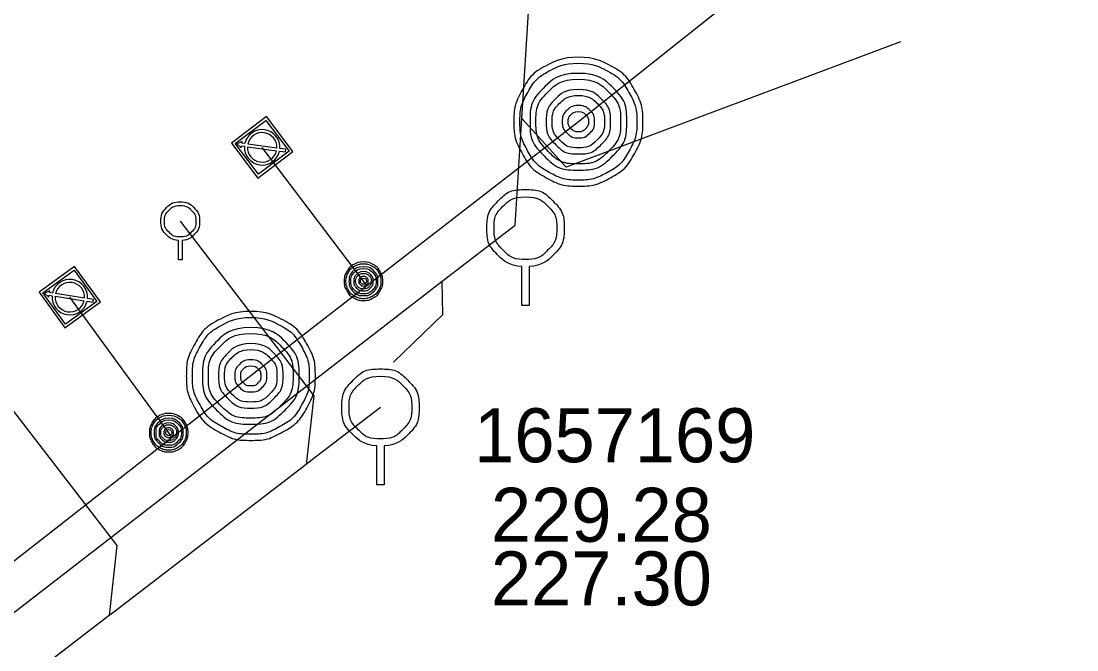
# Model space of a CAD drawing. Extents: x -595129 to -593591, y -1168385 to -1166898.
# Drawn here: x -594577.44 to -594550.08, y -1167330.38 to -1167314.08 of the extents above; entities that cross this region are included whole.
import ezdxf

# ---------------------------------------------------------------- set-up
doc = ezdxf.new("R2010")
doc.units = 0
for name, color, linetype in [('Default', 7, 'Continuous'), ('Identifikace', 7, 'Continuous'), ('Kanalizační přípojka', 7, 'Continuous'), ('Kanalizační stoka', 7, 'Continuous'), ('Kanalizační šachta', 7, 'Continuous'), ('Popis šachty', 7, 'Continuous'), ('V Odběrné místo', 7, 'Continuous'), ('V Přípojka', 7, 'Continuous'), ('V Řad', 7, 'Continuous')]:
    doc.layers.add(name, color=color, linetype=linetype)

msp = doc.modelspace()

# ---------------------------------------------------------------- linework, layer by layer
at = {"layer": 'Default'}
for points in [[(-594563.002, -1167315.017), (-594562.58, -1167315.017), (-594562.181, -1167315.232), (-594561.781, -1167315.448), (-594561.554, -1167315.85), (-594561.328, -1167316.253), (-594561.328, -1167316.69), (-594561.328, -1167317.124), (-594561.549, -1167317.522), (-594561.769, -1167317.919), (-594562.167, -1167318.14), (-594562.566, -1167318.36), (-594563.002, -1167318.36), (-594563.434, -1167318.36), (-594563.833, -1167318.14), (-594564.231, -1167317.919), (-594564.451, -1167317.522), (-594564.672, -1167317.124), (-594564.672, -1167316.69), (-594564.672, -1167316.253), (-594564.447, -1167315.85), (-594564.223, -1167315.448), (-594563.824, -1167315.232), (-594563.424, -1167315.017), (-594563.002, -1167315.017)], [(-594563.002, -1167315.173), (-594563.384, -1167315.173), (-594563.746, -1167315.369), (-594564.108, -1167315.564), (-594564.312, -1167315.928), (-594564.515, -1167316.293), (-594564.515, -1167316.69), (-594564.515, -1167317.083), (-594564.316, -1167317.443), (-594564.117, -1167317.803), (-594563.755, -1167318.003), (-594563.393, -1167318.203), (-594563.002, -1167318.203), (-594562.607, -1167318.203), (-594562.245, -1167318.003), (-594561.883, -1167317.803), (-594561.684, -1167317.443), (-594561.485, -1167317.083), (-594561.485, -1167316.69), (-594561.485, -1167316.293), (-594561.691, -1167315.928), (-594561.896, -1167315.564), (-594562.258, -1167315.369), (-594562.62, -1167315.173), (-594563.002, -1167315.173)], [(-594563.003, -1167315.435), (-594562.476, -1167315.435), (-594562.111, -1167315.802), (-594561.746, -1167316.169), (-594561.746, -1167316.69), (-594561.746, -1167317.209), (-594562.114, -1167317.576), (-594562.481, -1167317.942), (-594563.003, -1167317.942), (-594563.519, -1167317.942), (-594563.886, -1167317.576), (-594564.254, -1167317.209), (-594564.254, -1167316.69), (-594564.254, -1167316.169), (-594563.89, -1167315.802), (-594563.526, -1167315.435), (-594563.003, -1167315.435)], [(-594563.003, -1167315.588), (-594563.46, -1167315.588), (-594563.78, -1167315.909), (-594564.1, -1167316.23), (-594564.1, -1167316.685), (-594564.1, -1167317.141), (-594563.78, -1167317.461), (-594563.46, -1167317.782), (-594563.003, -1167317.782), (-594562.548, -1167317.782), (-594562.227, -1167317.461), (-594561.906, -1167317.141), (-594561.906, -1167316.685), (-594561.906, -1167316.23), (-594562.225, -1167315.909), (-594562.545, -1167315.588), (-594563.003, -1167315.588)], [(-594563.002, -1167315.853), (-594562.651, -1167315.853), (-594562.407, -1167316.097), (-594562.164, -1167316.342), (-594562.164, -1167316.69), (-594562.164, -1167317.036), (-594562.409, -1167317.28), (-594562.654, -1167317.524), (-594563.002, -1167317.524), (-594563.346, -1167317.524), (-594563.591, -1167317.28), (-594563.836, -1167317.036), (-594563.836, -1167316.69), (-594563.836, -1167316.342), (-594563.593, -1167316.097), (-594563.351, -1167315.853), (-594563.002, -1167315.853)], [(-594563.002, -1167316.008), (-594563.284, -1167316.008), (-594563.482, -1167316.206), (-594563.681, -1167316.404), (-594563.681, -1167316.687), (-594563.681, -1167316.969), (-594563.482, -1167317.167), (-594563.284, -1167317.366), (-594563.002, -1167317.366), (-594562.721, -1167317.366), (-594562.522, -1167317.167), (-594562.323, -1167316.969), (-594562.323, -1167316.687), (-594562.323, -1167316.404), (-594562.521, -1167316.206), (-594562.719, -1167316.008), (-594563.002, -1167316.008)], [(-594563.002, -1167316.27), (-594562.825, -1167316.27), (-594562.704, -1167316.393), (-594562.582, -1167316.515), (-594562.582, -1167316.688), (-594562.582, -1167316.861), (-594562.705, -1167316.984), (-594562.827, -1167317.106), (-594563.002, -1167317.106), (-594563.173, -1167317.106), (-594563.295, -1167316.984), (-594563.418, -1167316.861), (-594563.418, -1167316.688), (-594563.418, -1167316.515), (-594563.296, -1167316.393), (-594563.175, -1167316.27), (-594563.002, -1167316.27)], [(-594563.002, -1167316.427), (-594563.109, -1167316.427), (-594563.186, -1167316.502), (-594563.263, -1167316.577), (-594563.263, -1167316.688), (-594563.263, -1167316.796), (-594563.186, -1167316.873), (-594563.109, -1167316.95), (-594563.002, -1167316.95), (-594562.891, -1167316.95), (-594562.816, -1167316.873), (-594562.74, -1167316.796), (-594562.74, -1167316.688), (-594562.74, -1167316.577), (-594562.816, -1167316.502), (-594562.891, -1167316.427), (-594563.002, -1167316.427)], [(-594564.464, -1167320.446), (-594564.817, -1167320.417), (-594565.077, -1167320.157), (-594565.37, -1167319.866), (-594565.37, -1167319.452), (-594565.37, -1167319.036), (-594565.08, -1167318.743), (-594564.79, -1167318.45), (-594564.372, -1167318.45), (-594563.952, -1167318.45), (-594563.661, -1167318.743), (-594563.37, -1167319.036), (-594563.37, -1167319.452), (-594563.37, -1167319.866), (-594563.663, -1167320.157), (-594563.921, -1167320.417), (-594564.276, -1167320.446)], [(-594564.372, -1167318.636), (-594564.71, -1167318.636), (-594564.947, -1167318.873), (-594565.184, -1167319.11), (-594565.184, -1167319.448), (-594565.184, -1167319.786), (-594564.947, -1167320.023), (-594564.71, -1167320.261), (-594564.372, -1167320.261), (-594564.034, -1167320.261), (-594563.797, -1167320.023), (-594563.559, -1167319.786), (-594563.559, -1167319.448), (-594563.559, -1167319.11), (-594563.796, -1167318.873), (-594564.032, -1167318.636), (-594564.372, -1167318.636)], [(-594573.367, -1167319.768), (-594573.544, -1167319.753), (-594573.674, -1167319.624), (-594573.82, -1167319.478), (-594573.82, -1167319.271), (-594573.82, -1167319.063), (-594573.675, -1167318.916), (-594573.53, -1167318.77), (-594573.321, -1167318.77), (-594573.111, -1167318.77), (-594572.966, -1167318.916), (-594572.82, -1167319.063), (-594572.82, -1167319.271), (-594572.82, -1167319.478), (-594572.966, -1167319.624), (-594573.095, -1167319.753), (-594573.273, -1167319.768)], [(-594573.321, -1167318.863), (-594573.49, -1167318.863), (-594573.609, -1167318.981), (-594573.727, -1167319.1), (-594573.727, -1167319.269), (-594573.727, -1167319.438), (-594573.609, -1167319.557), (-594573.49, -1167319.675), (-594573.321, -1167319.675), (-594573.152, -1167319.675), (-594573.033, -1167319.557), (-594572.915, -1167319.438), (-594572.915, -1167319.269), (-594572.915, -1167319.1), (-594573.033, -1167318.981), (-594573.151, -1167318.863), (-594573.321, -1167318.863)], [(-594568.571, -1167320.323), (-594568.445, -1167320.323), (-594568.325, -1167320.388), (-594568.205, -1167320.452), (-594568.138, -1167320.573), (-594568.07, -1167320.693), (-594568.07, -1167320.824), (-594568.07, -1167320.954), (-594568.136, -1167321.073), (-594568.202, -1167321.192), (-594568.321, -1167321.258), (-594568.44, -1167321.324), (-594568.571, -1167321.324), (-594568.7, -1167321.324), (-594568.82, -1167321.258), (-594568.939, -1167321.192), (-594569.005, -1167321.073), (-594569.071, -1167320.954), (-594569.071, -1167320.824), (-594569.071, -1167320.693), (-594569.004, -1167320.573), (-594568.936, -1167320.452), (-594568.817, -1167320.388), (-594568.697, -1167320.323), (-594568.571, -1167320.323)], [(-594568.571, -1167320.37), (-594568.685, -1167320.37), (-594568.794, -1167320.429), (-594568.902, -1167320.487), (-594568.963, -1167320.596), (-594569.024, -1167320.705), (-594569.024, -1167320.824), (-594569.024, -1167320.942), (-594568.964, -1167321.05), (-594568.905, -1167321.158), (-594568.796, -1167321.217), (-594568.688, -1167321.277), (-594568.571, -1167321.277), (-594568.453, -1167321.277), (-594568.344, -1167321.217), (-594568.236, -1167321.158), (-594568.176, -1167321.05), (-594568.117, -1167320.942), (-594568.117, -1167320.824), (-594568.117, -1167320.705), (-594568.178, -1167320.596), (-594568.24, -1167320.487), (-594568.348, -1167320.429), (-594568.456, -1167320.37), (-594568.571, -1167320.37)], [(-594568.571, -1167320.448), (-594568.413, -1167320.448), (-594568.304, -1167320.558), (-594568.195, -1167320.668), (-594568.195, -1167320.824), (-594568.195, -1167320.98), (-594568.305, -1167321.089), (-594568.415, -1167321.199), (-594568.571, -1167321.199), (-594568.726, -1167321.199), (-594568.836, -1167321.089), (-594568.946, -1167320.98), (-594568.946, -1167320.824), (-594568.946, -1167320.668), (-594568.837, -1167320.558), (-594568.728, -1167320.448), (-594568.571, -1167320.448)], [(-594568.571, -1167320.494), (-594568.708, -1167320.494), (-594568.804, -1167320.59), (-594568.9, -1167320.686), (-594568.9, -1167320.823), (-594568.9, -1167320.959), (-594568.804, -1167321.055), (-594568.708, -1167321.151), (-594568.571, -1167321.151), (-594568.435, -1167321.151), (-594568.339, -1167321.055), (-594568.243, -1167320.959), (-594568.243, -1167320.823), (-594568.243, -1167320.686), (-594568.338, -1167320.59), (-594568.434, -1167320.494), (-594568.571, -1167320.494)], [(-594568.571, -1167320.574), (-594568.466, -1167320.574), (-594568.393, -1167320.647), (-594568.32, -1167320.72), (-594568.32, -1167320.824), (-594568.32, -1167320.928), (-594568.393, -1167321.001), (-594568.467, -1167321.074), (-594568.571, -1167321.074), (-594568.674, -1167321.074), (-594568.747, -1167321.001), (-594568.821, -1167320.928), (-594568.821, -1167320.824), (-594568.821, -1167320.72), (-594568.748, -1167320.647), (-594568.675, -1167320.574), (-594568.571, -1167320.574)], [(-594568.571, -1167320.62), (-594568.655, -1167320.62), (-594568.715, -1167320.679), (-594568.774, -1167320.739), (-594568.774, -1167320.823), (-594568.774, -1167320.908), (-594568.715, -1167320.967), (-594568.655, -1167321.027), (-594568.571, -1167321.027), (-594568.487, -1167321.027), (-594568.427, -1167320.967), (-594568.367, -1167320.908), (-594568.367, -1167320.823), (-594568.367, -1167320.739), (-594568.427, -1167320.679), (-594568.486, -1167320.62), (-594568.571, -1167320.62)], [(-594568.571, -1167320.699), (-594568.518, -1167320.699), (-594568.482, -1167320.735), (-594568.445, -1167320.772), (-594568.445, -1167320.824), (-594568.445, -1167320.876), (-594568.482, -1167320.912), (-594568.519, -1167320.949), (-594568.571, -1167320.949), (-594568.622, -1167320.949), (-594568.659, -1167320.912), (-594568.695, -1167320.876), (-594568.695, -1167320.824), (-594568.695, -1167320.772), (-594568.659, -1167320.735), (-594568.623, -1167320.699), (-594568.571, -1167320.699)], [(-594568.571, -1167320.746), (-594568.603, -1167320.746), (-594568.626, -1167320.768), (-594568.649, -1167320.791), (-594568.649, -1167320.824), (-594568.649, -1167320.856), (-594568.626, -1167320.879), (-594568.603, -1167320.902), (-594568.571, -1167320.902), (-594568.538, -1167320.902), (-594568.515, -1167320.879), (-594568.493, -1167320.856), (-594568.493, -1167320.824), (-594568.493, -1167320.791), (-594568.515, -1167320.768), (-594568.538, -1167320.746), (-594568.571, -1167320.746)], [(-594571.492, -1167321.607), (-594571.07, -1167321.607), (-594570.671, -1167321.822), (-594570.271, -1167322.038), (-594570.044, -1167322.44), (-594569.818, -1167322.843), (-594569.818, -1167323.28), (-594569.818, -1167323.714), (-594570.039, -1167324.112), (-594570.259, -1167324.509), (-594570.657, -1167324.73), (-594571.056, -1167324.95), (-594571.492, -1167324.95), (-594571.924, -1167324.95), (-594572.323, -1167324.73), (-594572.721, -1167324.509), (-594572.941, -1167324.112), (-594573.162, -1167323.714), (-594573.162, -1167323.28), (-594573.162, -1167322.843), (-594572.937, -1167322.44), (-594572.713, -1167322.038), (-594572.314, -1167321.822), (-594571.914, -1167321.607), (-594571.492, -1167321.607)], [(-594571.492, -1167321.763), (-594571.874, -1167321.763), (-594572.236, -1167321.959), (-594572.598, -1167322.154), (-594572.802, -1167322.518), (-594573.005, -1167322.883), (-594573.005, -1167323.28), (-594573.005, -1167323.673), (-594572.806, -1167324.033), (-594572.607, -1167324.393), (-594572.245, -1167324.593), (-594571.883, -1167324.793), (-594571.492, -1167324.793), (-594571.097, -1167324.793), (-594570.735, -1167324.593), (-594570.373, -1167324.393), (-594570.174, -1167324.033), (-594569.975, -1167323.673), (-594569.975, -1167323.28), (-594569.975, -1167322.883), (-594570.181, -1167322.518), (-594570.386, -1167322.154), (-594570.748, -1167321.959), (-594571.11, -1167321.763), (-594571.492, -1167321.763)], [(-594571.493, -1167322.025), (-594570.966, -1167322.025), (-594570.601, -1167322.392), (-594570.236, -1167322.759), (-594570.236, -1167323.28), (-594570.236, -1167323.799), (-594570.604, -1167324.166), (-594570.971, -1167324.532), (-594571.493, -1167324.532), (-594572.009, -1167324.532), (-594572.376, -1167324.166), (-594572.744, -1167323.799), (-594572.744, -1167323.28), (-594572.744, -1167322.759), (-594572.38, -1167322.392), (-594572.016, -1167322.025), (-594571.493, -1167322.025)], [(-594571.493, -1167322.178), (-594571.95, -1167322.178), (-594572.27, -1167322.499), (-594572.59, -1167322.82), (-594572.59, -1167323.275), (-594572.59, -1167323.731), (-594572.27, -1167324.051), (-594571.95, -1167324.372), (-594571.493, -1167324.372), (-594571.038, -1167324.372), (-594570.717, -1167324.051), (-594570.396, -1167323.731), (-594570.396, -1167323.275), (-594570.396, -1167322.82), (-594570.715, -1167322.499), (-594571.035, -1167322.178), (-594571.493, -1167322.178)], [(-594571.492, -1167322.443), (-594571.141, -1167322.443), (-594570.897, -1167322.687), (-594570.654, -1167322.932), (-594570.654, -1167323.28), (-594570.654, -1167323.626), (-594570.899, -1167323.87), (-594571.144, -1167324.114), (-594571.492, -1167324.114), (-594571.836, -1167324.114), (-594572.081, -1167323.87), (-594572.326, -1167323.626), (-594572.326, -1167323.28), (-594572.326, -1167322.932), (-594572.083, -1167322.687), (-594571.841, -1167322.443), (-594571.492, -1167322.443)], [(-594571.492, -1167322.598), (-594571.774, -1167322.598), (-594571.972, -1167322.796), (-594572.171, -1167322.994), (-594572.171, -1167323.277), (-594572.171, -1167323.559), (-594571.972, -1167323.757), (-594571.774, -1167323.956), (-594571.492, -1167323.956), (-594571.211, -1167323.956), (-594571.012, -1167323.757), (-594570.813, -1167323.559), (-594570.813, -1167323.277), (-594570.813, -1167322.994), (-594571.011, -1167322.796), (-594571.209, -1167322.598), (-594571.492, -1167322.598)], [(-594571.492, -1167322.86), (-594571.315, -1167322.86), (-594571.194, -1167322.983), (-594571.072, -1167323.105), (-594571.072, -1167323.278), (-594571.072, -1167323.451), (-594571.195, -1167323.574), (-594571.317, -1167323.696), (-594571.492, -1167323.696), (-594571.663, -1167323.696), (-594571.785, -1167323.574), (-594571.908, -1167323.451), (-594571.908, -1167323.278), (-594571.908, -1167323.105), (-594571.786, -1167322.983), (-594571.665, -1167322.86), (-594571.492, -1167322.86)], [(-594571.492, -1167323.017), (-594571.599, -1167323.017), (-594571.676, -1167323.092), (-594571.753, -1167323.167), (-594571.753, -1167323.278), (-594571.753, -1167323.386), (-594571.676, -1167323.463), (-594571.599, -1167323.54), (-594571.492, -1167323.54), (-594571.381, -1167323.54), (-594571.306, -1167323.463), (-594571.23, -1167323.386), (-594571.23, -1167323.278), (-594571.23, -1167323.167), (-594571.306, -1167323.092), (-594571.381, -1167323.017), (-594571.492, -1167323.017)], [(-594568.224, -1167325.096), (-594568.577, -1167325.067), (-594568.837, -1167324.807), (-594569.13, -1167324.516), (-594569.13, -1167324.102), (-594569.13, -1167323.686), (-594568.84, -1167323.393), (-594568.55, -1167323.1), (-594568.132, -1167323.1), (-594567.712, -1167323.1), (-594567.421, -1167323.393), (-594567.13, -1167323.686), (-594567.13, -1167324.102), (-594567.13, -1167324.516), (-594567.423, -1167324.807), (-594567.681, -1167325.067), (-594568.036, -1167325.096)], [(-594568.132, -1167323.286), (-594568.47, -1167323.286), (-594568.707, -1167323.523), (-594568.944, -1167323.76), (-594568.944, -1167324.098), (-594568.944, -1167324.436), (-594568.707, -1167324.673), (-594568.47, -1167324.911), (-594568.132, -1167324.911), (-594567.794, -1167324.911), (-594567.557, -1167324.673), (-594567.319, -1167324.436), (-594567.319, -1167324.098), (-594567.319, -1167323.76), (-594567.556, -1167323.523), (-594567.792, -1167323.286), (-594568.132, -1167323.286)], [(-594573.619, -1167324.25), (-594573.493, -1167324.25), (-594573.373, -1167324.315), (-594573.253, -1167324.379), (-594573.186, -1167324.5), (-594573.118, -1167324.62), (-594573.118, -1167324.751), (-594573.118, -1167324.881), (-594573.184, -1167325), (-594573.25, -1167325.119), (-594573.369, -1167325.185), (-594573.488, -1167325.251), (-594573.619, -1167325.251), (-594573.749, -1167325.251), (-594573.868, -1167325.185), (-594573.987, -1167325.119), (-594574.053, -1167325), (-594574.119, -1167324.881), (-594574.119, -1167324.751), (-594574.119, -1167324.62), (-594574.052, -1167324.5), (-594573.985, -1167324.379), (-594573.865, -1167324.315), (-594573.746, -1167324.25), (-594573.619, -1167324.25)], [(-594573.619, -1167324.297), (-594573.733, -1167324.297), (-594573.842, -1167324.355), (-594573.95, -1167324.414), (-594574.011, -1167324.523), (-594574.072, -1167324.632), (-594574.072, -1167324.751), (-594574.072, -1167324.869), (-594574.012, -1167324.977), (-594573.953, -1167325.084), (-594573.845, -1167325.144), (-594573.736, -1167325.204), (-594573.619, -1167325.204), (-594573.501, -1167325.204), (-594573.392, -1167325.144), (-594573.284, -1167325.084), (-594573.225, -1167324.977), (-594573.165, -1167324.869), (-594573.165, -1167324.751), (-594573.165, -1167324.632), (-594573.227, -1167324.523), (-594573.288, -1167324.414), (-594573.396, -1167324.355), (-594573.505, -1167324.297), (-594573.619, -1167324.297)], [(-594573.619, -1167324.375), (-594573.462, -1167324.375), (-594573.352, -1167324.485), (-594573.243, -1167324.595), (-594573.243, -1167324.751), (-594573.243, -1167324.907), (-594573.353, -1167325.016), (-594573.463, -1167325.126), (-594573.619, -1167325.126), (-594573.774, -1167325.126), (-594573.884, -1167325.016), (-594573.994, -1167324.907), (-594573.994, -1167324.751), (-594573.994, -1167324.595), (-594573.885, -1167324.485), (-594573.776, -1167324.375), (-594573.619, -1167324.375)], [(-594573.619, -1167324.421), (-594573.756, -1167324.421), (-594573.852, -1167324.517), (-594573.948, -1167324.613), (-594573.948, -1167324.75), (-594573.948, -1167324.886), (-594573.852, -1167324.982), (-594573.756, -1167325.078), (-594573.619, -1167325.078), (-594573.483, -1167325.078), (-594573.387, -1167324.982), (-594573.291, -1167324.886), (-594573.291, -1167324.75), (-594573.291, -1167324.613), (-594573.387, -1167324.517), (-594573.482, -1167324.421), (-594573.619, -1167324.421)], [(-594573.619, -1167324.5), (-594573.514, -1167324.5), (-594573.441, -1167324.574), (-594573.368, -1167324.647), (-594573.368, -1167324.751), (-594573.368, -1167324.855), (-594573.442, -1167324.928), (-594573.515, -1167325.001), (-594573.619, -1167325.001), (-594573.722, -1167325.001), (-594573.795, -1167324.928), (-594573.869, -1167324.855), (-594573.869, -1167324.751), (-594573.869, -1167324.647), (-594573.796, -1167324.574), (-594573.724, -1167324.5), (-594573.619, -1167324.5)], [(-594573.619, -1167324.547), (-594573.704, -1167324.547), (-594573.763, -1167324.606), (-594573.822, -1167324.666), (-594573.822, -1167324.75), (-594573.822, -1167324.835), (-594573.763, -1167324.894), (-594573.704, -1167324.953), (-594573.619, -1167324.953), (-594573.535, -1167324.953), (-594573.475, -1167324.894), (-594573.416, -1167324.835), (-594573.416, -1167324.75), (-594573.416, -1167324.666), (-594573.475, -1167324.606), (-594573.534, -1167324.547), (-594573.619, -1167324.547)], [(-594573.619, -1167324.626), (-594573.566, -1167324.626), (-594573.53, -1167324.662), (-594573.493, -1167324.699), (-594573.493, -1167324.751), (-594573.493, -1167324.802), (-594573.53, -1167324.839), (-594573.567, -1167324.876), (-594573.619, -1167324.876), (-594573.67, -1167324.876), (-594573.707, -1167324.839), (-594573.744, -1167324.802), (-594573.744, -1167324.751), (-594573.744, -1167324.699), (-594573.707, -1167324.662), (-594573.671, -1167324.626), (-594573.619, -1167324.626)], [(-594573.619, -1167324.672), (-594573.651, -1167324.672), (-594573.674, -1167324.695), (-594573.697, -1167324.717), (-594573.697, -1167324.751), (-594573.697, -1167324.783), (-594573.674, -1167324.806), (-594573.651, -1167324.829), (-594573.619, -1167324.829), (-594573.586, -1167324.829), (-594573.563, -1167324.806), (-594573.541, -1167324.783), (-594573.541, -1167324.751), (-594573.541, -1167324.717), (-594573.563, -1167324.695), (-594573.586, -1167324.672), (-594573.619, -1167324.672)]]:
    msp.add_open_spline(points, degree=3, dxfattribs=at)
at = {"layer": 'Kanalizační přípojka'}
for points in [[(-594554.65, -1167314.62), (-594563.32, -1167317.87), (-594564.47, -1167316.609)], [(-594573.32, -1167319.27), (-594569.86, -1167323.8), (-594570.059, -1167325.58)], [(-594567.79, -1167322.92), (-594566.51, -1167321.69), (-594566.531, -1167320.826)], [(-594578.41, -1167323.21), (-594574.96, -1167327.68), (-594575.16, -1167329.493)]]:
    msp.add_lwpolyline(points, dxfattribs=at)
at = {"layer": 'Kanalizační stoka'}
for points in [[(-594564.636, -1167319.367), (-594564.47, -1167316.609), (-594563.762, -1167305.284)], [(-594594.34, -1167342.32), (-594589.151, -1167338.309), (-594578.642, -1167330.187), (-594566.531, -1167320.826), (-594564.636, -1167319.367)], [(-594568.13, -1167324.1), (-594569.778, -1167325.364), (-594570.059, -1167325.58), (-594575.04, -1167329.401), (-594575.16, -1167329.493), (-594579.707, -1167332.981), (-594579.896, -1167333.126), (-594585.151, -1167337.156), (-594585.182, -1167337.18), (-594590.246, -1167341.065), (-594590.406, -1167341.187), (-594595.365, -1167344.991), (-594595.386, -1167345.007), (-594600.5, -1167348.93)]]:
    msp.add_lwpolyline(points, dxfattribs=at)
at = {"layer": 'Kanalizační šachta'}
for points in [[(-594573.273, -1167319.768), (-594573.273, -1167320.27), (-594573.367, -1167320.27), (-594573.367, -1167319.768)], [(-594564.276, -1167320.446), (-594564.276, -1167321.45), (-594564.464, -1167321.45), (-594564.464, -1167320.446)], [(-594568.036, -1167325.096), (-594568.036, -1167326.1), (-594568.224, -1167326.1), (-594568.224, -1167325.096)]]:
    msp.add_lwpolyline(points, dxfattribs=at)
at = {"layer": 'V Odběrné místo'}
for p, q in [((-594571.579, -1167317.338), (-594570.823, -1167317.442)), ((-594570.813, -1167317.372), (-594571.569, -1167317.267)), ((-594575.8, -1167321.261), (-594576.554, -1167321.142)), ((-594576.565, -1167321.213), (-594575.81, -1167321.331))]:
    msp.add_line(p, q, dxfattribs=at)
for points in [[(-594570.398, -1167317.465), (-594571.085, -1167316.556), (-594571.994, -1167317.244), (-594571.307, -1167318.153)], [(-594570.497, -1167317.451), (-594571.293, -1167318.053), (-594571.895, -1167317.258), (-594571.099, -1167316.656)], [(-594575.386, -1167321.361), (-594576.057, -1167320.44), (-594576.978, -1167321.112), (-594576.307, -1167322.033)], [(-594575.485, -1167321.346), (-594576.291, -1167321.934), (-594576.879, -1167321.128), (-594576.073, -1167320.54)]]:
    msp.add_lwpolyline(points, close=True, dxfattribs=at)
for points in [[(-594571.645, -1167317.256), (-594571.722, -1167317.246), (-594571.716, -1167317.205), (-594571.853, -1167317.266), (-594571.738, -1167317.362), (-594571.732, -1167317.317), (-594571.655, -1167317.327)], [(-594570.747, -1167317.453), (-594570.592, -1167317.474), (-594570.582, -1167317.404), (-594570.737, -1167317.382)], [(-594576.63, -1167321.131), (-594576.706, -1167321.119), (-594576.699, -1167321.078), (-594576.837, -1167321.137), (-594576.724, -1167321.235), (-594576.717, -1167321.189), (-594576.64, -1167321.201)], [(-594575.735, -1167321.343), (-594575.58, -1167321.367), (-594575.569, -1167321.297), (-594575.723, -1167321.273)]]:
    msp.add_lwpolyline(points, dxfattribs=at)
for centre, radius, start, end in [((-594571.196, -1167317.354), 0.46, 356.5384, 167.6936), ((-594571.196, -1167317.354), 0.383, 357.4292, 166.7497), ((-594571.196, -1167317.354), 0.46, 176.5891, 347.6433), ((-594571.196, -1167317.354), 0.383, 177.4799, 346.7526), ((-594576.182, -1167321.237), 0.46, 355.5301, 166.6853), ((-594576.182, -1167321.237), 0.383, 356.4208, 165.7413), ((-594576.182, -1167321.237), 0.46, 175.5808, 346.635), ((-594576.182, -1167321.237), 0.383, 176.4716, 345.7443)]:
    msp.add_arc(centre, radius, start, end, dxfattribs=at)
at = {"layer": 'V Přípojka'}
for points in [[(-594568.481, -1167320.944), (-594568.57, -1167320.824), (-594571.196, -1167317.354)], [(-594573.53, -1167324.872), (-594573.619, -1167324.751), (-594576.182, -1167321.237)]]:
    msp.add_lwpolyline(points, dxfattribs=at)
at = {"layer": 'V Řad'}
msp.add_lwpolyline([(-594559.721, -1167288.497), (-594560.82, -1167295.8), (-594560.22, -1167296.48), (-594553.19, -1167297.46), (-594550.08, -1167301.16), (-594550.43, -1167306.69), (-594563, -1167316.69), (-594568.481, -1167320.944), (-594571.49, -1167323.28), (-594573.53, -1167324.872), (-594578.495, -1167328.758), (-594583.46, -1167332.632), (-594588.74, -1167336.755), (-594593.537, -1167340.523), (-594602.19, -1167347.31), (-594604.637, -1167349.22), (-594609.603, -1167353.096), (-594614.808, -1167357.16), (-594615.446, -1167357.657), (-594619.691, -1167360.971), (-594630.47, -1167369.42), (-594632.795, -1167371.245)], dxfattribs=at)

# ---------------------------------------------------------------- texts
at = {"layer": 'Identifikace'}
msp.add_text('1657169', height=1.4, dxfattribs=at).set_placement((-594565.702, -1167325.518))
at = {"layer": 'Popis šachty'}
for s, p in [('229.28', (-594565.267, -1167327.58)), ('227.30', (-594565.267, -1167329.23))]:
    msp.add_text(s, height=1.4, dxfattribs=at).set_placement(p)

doc.saveas('drawing.dxf')
